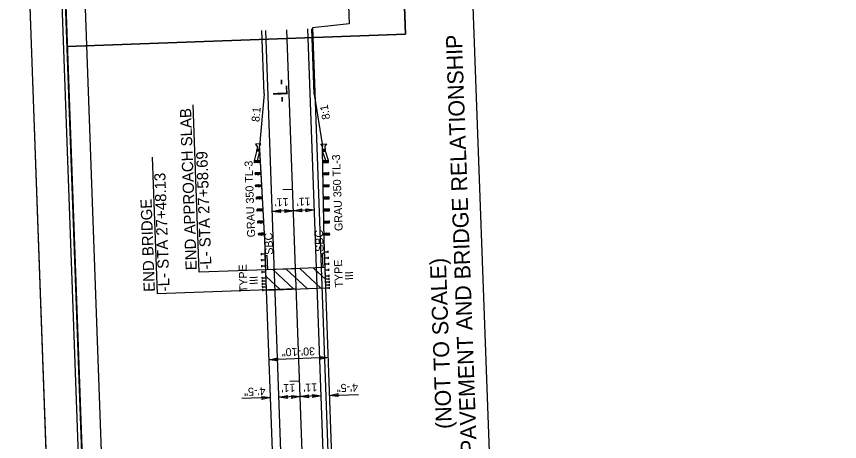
# Model space of a CAD drawing. Extents: x 2065256 to 2066537, y 145527 to 147314.
# Drawn here: x 2065382 to 2065896, y 146742 to 147008 of the extents above; entities that cross this region are included whole.
import ezdxf

# ---------------------------------------------------------------- set-up
doc = ezdxf.new("R2010")
doc.units = 0
for name, color, linetype in [('Prop Approach Slab', 7, 'Continuous'), ('Prop Approach Slab Hatching', 7, 'Continuous'), ('Prop Conc Shoulder Berm Gutter', 7, 'Continuous'), ('Prop Dimension', 7, 'Continuous'), ('Prop Dimension Text', 7, 'Continuous'), ('Prop EOT', 7, 'Continuous'), ('Prop Guardrail', 7, 'Continuous'), ('Prop Guardrail Anchor Unit CELL', 7, 'Continuous'), ('Prop Horizontal Alignment', 7, 'Continuous'), ('Prop Horizontal Alignment Station Label', 7, 'Continuous'), ('Prop Horizontal Alignment Tick Small', 7, 'Continuous'), ('Prop Paved Shoulder', 7, 'Continuous'), ('Prop Roadway Bridge', 7, 'Continuous'), ('Prop Structure Anchor Unit CELL', 7, 'Continuous'), ('Prop Terminator CELL', 7, 'Continuous'), ('Sheet Clip Boundary CELL', 7, 'Continuous'), ('Sheet Cutting Line CELL', 7, 'Continuous'), ('Sheet Layout Plan Border', 7, 'Continuous'), ('Sheet Plan CELL', 7, 'Continuous'), ('Sheet Plan Layout CELL', 7, 'Continuous'), ('Sheet Plot Border Inside CELL', 7, 'Continuous'), ('Sheet Plot Border Outside CELL', 7, 'Continuous')]:
    doc.layers.add(name, color=color, linetype=linetype)

msp = doc.modelspace()

# ---------------------------------------------------------------- linework, layer by layer
at = {"layer": 'Prop Approach Slab'}
for p, q in [((2065574.76, 146851.17), (2065537.78, 146849.83)), ((2065538.24, 146837.17), (2065537.78, 146849.83)), ((2065575.22, 146838.51), (2065574.76, 146851.17))]:
    msp.add_line(p, q, dxfattribs=at)
at = {"layer": 'Prop Approach Slab Hatching'}
for p, q in [((2065555.2, 146837.78), (2065542.08, 146849.99)), ((2065563.68, 146838.09), (2065550.56, 146850.3)), ((2065572.16, 146838.4), (2065559.04, 146850.6)), ((2065575.02, 146843.93), (2065567.52, 146850.91)), ((2065546.72, 146837.48), (2065537.93, 146845.65))]:
    msp.add_line(p, q, dxfattribs=at)
at = {"layer": 'Prop Conc Shoulder Berm Gutter'}
for p, q in [((2065573.56, 146851.13), (2065573.24, 146859.93)), ((2065538.98, 146849.88), (2065538.66, 146858.68))]:
    msp.add_line(p, q, dxfattribs=at)
at = {"layer": 'Prop Dimension'}
for p, q in [((2065683.84, 146559.92), (2065666.92, 147028.09)), ((2065441.7, 146551.17), (2065424.78, 147019.34)), ((2065568.15, 146887.25), (2065541.77, 146886.3)), ((2065576.79, 146794.98), (2065539.82, 146793.64)), ((2065540.67, 146769.94), (2065522.68, 146769.29)), ((2065572.35, 146771.08), (2065545.97, 146770.13)), ((2065577.65, 146771.27), (2065595.64, 146771.92))]:
    msp.add_line(p, q, dxfattribs=at)
at = {"layer": 'Prop EOT'}
for p, q in [((2065547.82, 146718.86), (2065537.68, 146999.49)), ((2065574.2, 146719.81), (2065564.06, 147000.44))]:
    msp.add_line(p, q, dxfattribs=at)
at = {"layer": 'Prop Guardrail'}
for p, q in [((2065537.21, 146865.72), (2065537.43, 146859.66)), ((2065574.4, 146860.99), (2065574.13, 146868.49))]:
    msp.add_line(p, q, dxfattribs=at)
at = {"layer": 'Prop Guardrail Anchor Unit CELL'}
for p, q in [((2065534.75, 146928.52), (2065531.23, 146928.38)), ((2065531.23, 146928.38), (2065532.31, 146927.01)), ((2065532.31, 146927.01), (2065532.4, 146924.56)), ((2065533.77, 146927.07), (2065534.75, 146928.52)), ((2065533.87, 146924.61), (2065533.77, 146927.07)), ((2065572.15, 146928.45), (2065575.68, 146928.57)), ((2065573.23, 146927.08), (2065572.15, 146928.45)), ((2065573.32, 146924.62), (2065573.23, 146927.08)), ((2065575.68, 146928.57), (2065574.7, 146927.13)), ((2065574.7, 146927.13), (2065574.78, 146924.67)), ((2065530.65, 146917.9), (2065532.2, 146923.88)), ((2065533.93, 146925.18), (2065532.13, 146925.08)), ((2065532.2, 146923.88), (2065532.13, 146925.08)), ((2065532.13, 146925.08), (2065533.99, 146923.98)), ((2065532.2, 146923.88), (2065532.16, 146924.48)), ((2065533.93, 146925.18), (2065532.2, 146923.88)), ((2065533.99, 146923.98), (2065532.2, 146923.88)), ((2065532.4, 146924.56), (2065533.13, 146924.58)), ((2065532.49, 146918.01), (2065533.99, 146923.98)), ((2065533.13, 146924.58), (2065533.87, 146924.61)), ((2065537.11, 146868.57), (2065533.96, 146924.58)), ((2065573.22, 146925.18), (2065575.02, 146925.21)), ((2065573.22, 146925.18), (2065575.04, 146924.01)), ((2065574.13, 146868.49), (2065573.23, 146924.58)), ((2065575.02, 146925.21), (2065573.24, 146923.98)), ((2065573.24, 146923.98), (2065575.04, 146924.01)), ((2065575.17, 146918.13), (2065573.24, 146923.98)), ((2065574.05, 146924.65), (2065573.32, 146924.62)), ((2065574.78, 146924.67), (2065574.05, 146924.65)), ((2065575.04, 146924.01), (2065575.02, 146925.21)), ((2065575.04, 146924.01), (2065575.03, 146924.61)), ((2065577.01, 146918.16), (2065575.04, 146924.01)), ((2065534.32, 146918.11), (2065530.65, 146917.9)), ((2065530.72, 146916.7), (2065530.65, 146917.9)), ((2065530.65, 146917.9), (2065532.55, 146916.81)), ((2065532.49, 146918.01), (2065530.72, 146916.7)), ((2065534.39, 146916.91), (2065530.72, 146916.7)), ((2065532.55, 146916.81), (2065532.49, 146918.01)), ((2065534.39, 146916.91), (2065532.49, 146918.01)), ((2065532.55, 146916.81), (2065534.32, 146918.11)), ((2065573.33, 146918.1), (2065577.01, 146918.16)), ((2065575.19, 146916.93), (2065573.33, 146918.1)), ((2065573.35, 146916.9), (2065575.17, 146918.13)), ((2065573.35, 146916.9), (2065577.03, 146916.96)), ((2065575.19, 146916.93), (2065575.17, 146918.13)), ((2065575.17, 146918.13), (2065577.03, 146916.96)), ((2065577.01, 146918.16), (2065575.19, 146916.93)), ((2065577.03, 146916.96), (2065577.01, 146918.16)), ((2065534.75, 146910.56), (2065531.15, 146910.36)), ((2065531.22, 146909.16), (2065531.15, 146910.36)), ((2065531.15, 146910.36), (2065533.02, 146909.26)), ((2065532.95, 146910.46), (2065531.22, 146909.16)), ((2065534.81, 146909.36), (2065531.22, 146909.16)), ((2065533.02, 146909.26), (2065532.95, 146910.46)), ((2065534.81, 146909.36), (2065532.95, 146910.46)), ((2065533.02, 146909.26), (2065534.75, 146910.56)), ((2065573.45, 146910.54), (2065577.05, 146910.6)), ((2065575.27, 146909.37), (2065573.45, 146910.54)), ((2065573.47, 146909.34), (2065575.26, 146910.57)), ((2065573.47, 146909.34), (2065577.07, 146909.4)), ((2065575.27, 146909.37), (2065575.26, 146910.57)), ((2065575.26, 146910.57), (2065577.07, 146909.4)), ((2065577.05, 146910.6), (2065575.27, 146909.37)), ((2065577.07, 146909.4), (2065577.05, 146910.6)), ((2065535.17, 146903.01), (2065531.41, 146902.8)), ((2065531.48, 146901.6), (2065531.41, 146902.8)), ((2065531.41, 146902.8), (2065533.36, 146901.7)), ((2065533.29, 146902.9), (2065531.48, 146901.6)), ((2065535.24, 146901.81), (2065531.48, 146901.6)), ((2065533.36, 146901.7), (2065533.29, 146902.9)), ((2065535.24, 146901.81), (2065533.29, 146902.9)), ((2065533.36, 146901.7), (2065535.17, 146903.01)), ((2065573.58, 146902.98), (2065577.34, 146903.04)), ((2065575.48, 146901.81), (2065573.58, 146902.98)), ((2065573.6, 146901.78), (2065575.46, 146903.01)), ((2065573.6, 146901.78), (2065577.36, 146901.84)), ((2065575.48, 146901.81), (2065575.46, 146903.01)), ((2065575.46, 146903.01), (2065577.36, 146901.84)), ((2065577.34, 146903.04), (2065575.48, 146901.81)), ((2065577.36, 146901.84), (2065577.34, 146903.04)), ((2065535.6, 146895.46), (2065531.96, 146895.25)), ((2065533.84, 146894.16), (2065535.6, 146895.46)), ((2065535.66, 146894.26), (2065535.6, 146895.46)), ((2065573.7, 146895.42), (2065577.34, 146895.48)), ((2065573.72, 146894.22), (2065575.52, 146895.45)), ((2065575.54, 146894.25), (2065575.52, 146895.45)), ((2065575.52, 146895.45), (2065577.36, 146894.28)), ((2065577.34, 146895.48), (2065575.54, 146894.25)), ((2065577.36, 146894.28), (2065577.34, 146895.48)), ((2065532.03, 146894.06), (2065531.96, 146895.25)), ((2065531.96, 146895.25), (2065533.84, 146894.16)), ((2065533.78, 146895.36), (2065532.03, 146894.06)), ((2065535.66, 146894.26), (2065532.03, 146894.06)), ((2065533.84, 146894.16), (2065533.78, 146895.36)), ((2065535.66, 146894.26), (2065533.78, 146895.36)), ((2065573.72, 146894.22), (2065573.7, 146895.42)), ((2065575.54, 146894.25), (2065573.7, 146895.42)), ((2065573.72, 146894.22), (2065577.36, 146894.28)), ((2065536.02, 146887.91), (2065532.37, 146887.7)), ((2065532.44, 146886.51), (2065532.37, 146887.7)), ((2065532.37, 146887.7), (2065534.26, 146886.61)), ((2065534.19, 146887.81), (2065532.44, 146886.51)), ((2065536.09, 146886.71), (2065532.44, 146886.51)), ((2065534.26, 146886.61), (2065534.19, 146887.81)), ((2065536.09, 146886.71), (2065534.19, 146887.81)), ((2065534.26, 146886.61), (2065536.02, 146887.91)), ((2065573.82, 146887.86), (2065577.48, 146887.92)), ((2065575.67, 146886.69), (2065573.82, 146887.86)), ((2065573.84, 146886.66), (2065575.65, 146887.89)), ((2065573.84, 146886.66), (2065577.5, 146886.72)), ((2065575.67, 146886.69), (2065575.65, 146887.89)), ((2065575.65, 146887.89), (2065577.5, 146886.72)), ((2065577.48, 146887.92), (2065575.67, 146886.69)), ((2065577.5, 146886.72), (2065577.48, 146887.92)), ((2065536.44, 146880.36), (2065532.79, 146880.15)), ((2065532.85, 146878.96), (2065532.79, 146880.15)), ((2065532.79, 146880.15), (2065534.68, 146879.06)), ((2065534.62, 146880.26), (2065532.85, 146878.96)), ((2065534.68, 146879.06), (2065534.62, 146880.26)), ((2065536.51, 146879.16), (2065534.62, 146880.26)), ((2065534.68, 146879.06), (2065536.44, 146880.36)), ((2065573.94, 146880.3), (2065577.61, 146880.36)), ((2065575.79, 146879.13), (2065573.94, 146880.3)), ((2065573.96, 146879.1), (2065575.77, 146880.33)), ((2065575.79, 146879.13), (2065575.77, 146880.33)), ((2065575.77, 146880.33), (2065577.62, 146879.16)), ((2065577.61, 146880.36), (2065575.79, 146879.13)), ((2065577.62, 146879.16), (2065577.61, 146880.36)), ((2065536.51, 146879.16), (2065532.85, 146878.96)), ((2065573.96, 146879.1), (2065577.62, 146879.16)), ((2065536.87, 146872.81), (2065533.27, 146872.61)), ((2065533.34, 146871.41), (2065533.27, 146872.61)), ((2065533.27, 146872.61), (2065535.14, 146871.51)), ((2065535.07, 146872.71), (2065533.34, 146871.41)), ((2065536.94, 146871.61), (2065533.34, 146871.41)), ((2065536.87, 146872.81), (2065535.07, 146872.71)), ((2065535.14, 146871.51), (2065535.07, 146872.71)), ((2065535.07, 146872.71), (2065536.94, 146871.61)), ((2065535.14, 146871.51), (2065536.87, 146872.81)), ((2065536.94, 146871.61), (2065536.87, 146872.81)), ((2065574.06, 146872.74), (2065577.66, 146872.8)), ((2065574.06, 146872.74), (2065575.87, 146872.77)), ((2065574.08, 146871.54), (2065574.06, 146872.74)), ((2065575.88, 146871.57), (2065574.06, 146872.74)), ((2065575.87, 146872.77), (2065574.08, 146871.54)), ((2065574.08, 146871.54), (2065577.68, 146871.6)), ((2065575.88, 146871.57), (2065575.87, 146872.77)), ((2065575.87, 146872.77), (2065577.68, 146871.6)), ((2065577.66, 146872.8), (2065575.88, 146871.57)), ((2065577.68, 146871.6), (2065577.66, 146872.8))]:
    msp.add_line(p, q, dxfattribs=at)
at = {"layer": 'Prop Horizontal Alignment'}
msp.add_line((2065566.09, 146578.81), (2065550.87, 146999.96), dxfattribs=at)
at = {"layer": 'Prop Horizontal Alignment Station Label'}
for p, q in [((2065496.09, 146848.33), (2065492.3, 146953.02)), ((2065466.78, 146920.23), (2065469.88, 146834.7)), ((2065556.27, 146850.5), (2065496.09, 146848.33)), ((2065556.73, 146837.84), (2065469.88, 146834.7))]:
    msp.add_line(p, q, dxfattribs=at)
at = {"layer": 'Prop Horizontal Alignment Tick Small'}
for p, q in [((2065554.48, 146900.04), (2065548.48, 146899.83)), ((2065558.82, 146780.12), (2065552.82, 146779.9))]:
    msp.add_line(p, q, dxfattribs=at)
at = {"layer": 'Prop Paved Shoulder'}
for p, q in [((2065536.71, 146959.93), (2065535.28, 146999.4)), ((2065567.94, 146959.64), (2065566.46, 147000.53)), ((2065536.71, 146959.93), (2065533.77, 146927.07)), ((2065567.94, 146959.64), (2065573.23, 146927.08)), ((2065537.78, 146849.83), (2065537.11, 146868.57)), ((2065574.76, 146851.17), (2065574.13, 146868.49)), ((2065574.44, 146859.97), (2065573.24, 146859.93)), ((2065538.66, 146858.68), (2065537.47, 146858.64))]:
    msp.add_line(p, q, dxfattribs=at)
for points in [[(2065537.11, 146868.57), (2065533.93, 146925.18), (2065533.77, 146927.07)], [(2065574.13, 146868.49), (2065573.22, 146925.18), (2065573.23, 146927.08)]]:
    msp.add_lwpolyline(points, dxfattribs=at)
at = {"layer": 'Prop Roadway Bridge'}
for p, q in [((2065538.24, 146837.17), (2065575.22, 146838.51)), ((2065542.07, 146731.33), (2065538.24, 146837.17)), ((2065579.04, 146732.66), (2065575.22, 146838.51))]:
    msp.add_line(p, q, dxfattribs=at)
at = {"layer": 'Prop Structure Anchor Unit CELL'}
for p, q in [((2065535.06, 146858.88), (2065535.01, 146860.26)), ((2065537.43, 146859.66), (2065535.03, 146859.57)), ((2065538.24, 146837.17), (2065537.43, 146859.66)), ((2065574.4, 146860.99), (2065576.8, 146861.08)), ((2065575.22, 146838.51), (2065574.4, 146860.99)), ((2065576.83, 146860.39), (2065576.78, 146861.77)), ((2065535.19, 146855.13), (2065535.14, 146856.51)), ((2065537.56, 146855.91), (2065535.17, 146855.82)), ((2065574.54, 146857.24), (2065576.94, 146857.33)), ((2065576.96, 146856.64), (2065576.91, 146858.02)), ((2065577.1, 146852.9), (2065577.05, 146854.27)), ((2065535.33, 146851.39), (2065535.28, 146852.76)), ((2065537.7, 146852.16), (2065535.3, 146852.07)), ((2065574.68, 146853.5), (2065577.07, 146853.58)), ((2065574.81, 146849.75), (2065577.21, 146849.84)), ((2065577.23, 146849.15), (2065577.18, 146850.52)), ((2065535.46, 146847.64), (2065535.41, 146849.01)), ((2065537.84, 146848.41), (2065535.44, 146848.33)), ((2065535.6, 146843.89), (2065535.55, 146845.27)), ((2065537.97, 146844.67), (2065535.57, 146844.58)), ((2065574.95, 146846), (2065577.34, 146846.09)), ((2065575.01, 146844.13), (2065577.41, 146844.21)), ((2065577.37, 146845.4), (2065577.32, 146846.78)), ((2065577.44, 146843.53), (2065577.39, 146844.9)), ((2065535.66, 146842.02), (2065535.62, 146843.39)), ((2065538.04, 146842.79), (2065535.64, 146842.7)), ((2065535.73, 146840.14), (2065535.68, 146841.52)), ((2065538.11, 146840.92), (2065535.71, 146840.83)), ((2065535.8, 146838.27), (2065535.75, 146839.64)), ((2065538.17, 146839.04), (2065535.78, 146838.96)), ((2065575.08, 146842.25), (2065577.48, 146842.34)), ((2065575.15, 146840.38), (2065577.55, 146840.47)), ((2065577.51, 146841.65), (2065577.46, 146843.03)), ((2065577.57, 146839.78), (2065577.52, 146841.15)), ((2065577.64, 146837.91), (2065577.59, 146839.28)), ((2065535.87, 146836.4), (2065535.82, 146837.77)), ((2065538.24, 146837.17), (2065535.84, 146837.08)), ((2065575.22, 146838.51), (2065577.62, 146838.59))]:
    msp.add_line(p, q, dxfattribs=at)
at = {"layer": 'Prop Terminator CELL'}
for points in [[(2065547.2, 146885.56), (2065541.77, 146886.3), (2065547.16, 146887.45), (2065546.51, 146886.47)], [(2065549.53, 146887.51), (2065554.96, 146886.78), (2065549.57, 146885.62), (2065550.22, 146886.6)], [(2065560.39, 146886.04), (2065554.96, 146886.78), (2065560.35, 146887.93), (2065559.7, 146886.95)], [(2065562.72, 146887.99), (2065568.15, 146887.25), (2065562.76, 146886.1), (2065563.41, 146887.08)], [(2065545.25, 146792.9), (2065539.82, 146793.64), (2065545.21, 146794.79), (2065544.55, 146793.81)], [(2065571.36, 146795.71), (2065576.79, 146794.98), (2065571.4, 146793.82), (2065572.05, 146794.8)], [(2065583.08, 146770.54), (2065577.65, 146771.27), (2065583.04, 146772.43), (2065582.38, 146771.44)], [(2065535.24, 146770.67), (2065540.67, 146769.94), (2065535.28, 146768.78), (2065535.93, 146769.77)], [(2065551.4, 146769.39), (2065545.97, 146770.13), (2065551.36, 146771.28), (2065550.71, 146770.3)], [(2065553.73, 146771.34), (2065559.16, 146770.6), (2065553.77, 146769.45), (2065554.42, 146770.43)], [(2065564.59, 146769.87), (2065559.16, 146770.6), (2065564.55, 146771.76), (2065563.9, 146770.78)], [(2065566.92, 146771.82), (2065572.35, 146771.08), (2065566.96, 146769.93), (2065567.61, 146770.91)]]:
    msp.add_lwpolyline(points, close=True, dxfattribs=at)
at = {"layer": 'Sheet Clip Boundary CELL'}
msp.add_lwpolyline([(2066225.3, 145855.32), (2066356.28, 145860.05), (2066306.24, 147244.42), (2065582.18, 147218.25), (2065589.94, 147003.52), (2065566.99, 147001.07), (2065609.27, 145831.43)], close=True, dxfattribs=at)
at = {"layer": 'Sheet Cutting Line CELL'}
msp.add_line((2065381.93, 147244.73), (2065442.74, 145562.33), dxfattribs=at)
at = {"layer": 'Sheet Layout Plan Border'}
msp.add_lwpolyline([(2066506.71, 145817.42), (2066456.14, 147216.52), (2065618.17, 147186.22), (2065625.01, 146997.09), (2065413.66, 146989.45), (2065457.4, 145779.49)], close=True, dxfattribs=at)
at = {"layer": 'Sheet Plan CELL'}
for points in [[(2065405.01, 147228.58), (2065459.2, 145729.52), (2066508.52, 145767.45), (2066454.33, 147266.48)], [(2066508.52, 145767.45), (2065459.23, 145729.49), (2065412.23, 147028.63), (2065562.19, 147034.07), (2065554.98, 147233.97), (2066454.33, 147266.48)]]:
    msp.add_lwpolyline(points, close=True, dxfattribs=at)
at = {"layer": 'Sheet Plan Layout CELL'}
for points in [[(2065459.23, 145729.49), (2066508.52, 145767.45), (2066454.33, 147266.47), (2065616.37, 147236.18), (2065625.01, 146997.09), (2065413.66, 146989.45)], [(2065625.01, 146997.09), (2065616.36, 147236.2), (2065405.01, 147228.59), (2065413.66, 146989.45)]]:
    msp.add_lwpolyline(points, close=True, dxfattribs=at)
at = {"layer": 'Sheet Plot Border Inside CELL'}
msp.add_lwpolyline([(2066516.57, 145614.15), (2066456.38, 147279.05), (2065402.08, 147240.95), (2065462.26, 145576.04)], close=True, dxfattribs=at)
at = {"layer": 'Sheet Plot Border Outside CELL'}
msp.add_lwpolyline([(2066537.03, 145601.88), (2066476.21, 147284.29), (2065381.93, 147244.73), (2065442.74, 145562.33)], close=True, dxfattribs=at)

# ---------------------------------------------------------------- texts
at = {"layer": 'Prop Dimension'}
for s, p in [('DETAIL SHOWING PAVEMENT AND BRIDGE RELATIONSHIP', (2065674.05, 146615.35)), ('(NOT TO SCALE)', (2065654.11, 146750.5))]:
    msp.add_text(s, height=10, rotation=92.0702, dxfattribs=at).set_placement(p)
at = {"layer": 'Prop Dimension Text'}
for s, rotation, p in [('8:1', 100.0087, (2065578, 146944.21)), ('8:1', 84.9938, (2065533.78, 146942.1)), ("11'", 182.0702, (2065551.87, 146894.76)), ("11'", 182.0702, (2065565.63, 146895.04)), ('SBC', 92.0702, (2065542.33, 146859.35)), ('SBC', 92.0702, (2065573.93, 146861.14)), ('30\'-10"', 182.0702, (2065568.42, 146801.44)), ("11'", 182.0702, (2065556.07, 146778.59)), ("11'", 182.0702, (2065569.83, 146778.87)), ('4\'-5"', 182.0702, (2065595.35, 146778.81)), ('4\'-5"', 182.0702, (2065537.46, 146776.44))]:
    msp.add_text(s, height=5, rotation=rotation, dxfattribs=at).set_placement(p)
at = {"layer": 'Prop Guardrail Anchor Unit CELL'}
for p in [(2065585.83, 146874.14), (2065531.14, 146870.2)]:
    msp.add_text('GRAU 350 TL-3', height=5, rotation=92.0702, dxfattribs=at).set_placement(p)
at = {"layer": 'Prop Horizontal Alignment Station Label'}
for s, height, p in [('-L-', 9.103, (2065551.57, 146954.52)), ('END APPROACH SLAB', 7, (2065494.67, 146849.67)), ('-L- STA 27+58.69', 7, (2065503.84, 146850)), ('-L- STA 27+48.13', 7, (2065477.64, 146836.49)), ('END BRIDGE', 7, (2065468.47, 146836.16))]:
    msp.add_text(s, height=height, rotation=92.0702, dxfattribs=at).set_placement(p)
at = {"layer": 'Prop Structure Anchor Unit CELL'}
for s, p in [('TYPE', (2065585.99, 146838.82)), ('TYPE', (2065526.36, 146835.89)), ('III', (2065532.75, 146840.52)), ('III', (2065592.38, 146843.45))]:
    msp.add_text(s, height=5, rotation=92.0702, dxfattribs=at).set_placement(p)

doc.saveas('drawing.dxf')
